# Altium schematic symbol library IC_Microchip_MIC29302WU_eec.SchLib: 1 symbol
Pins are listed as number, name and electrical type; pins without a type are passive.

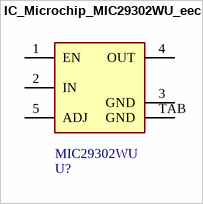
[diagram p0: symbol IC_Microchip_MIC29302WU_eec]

## IC_Microchip_MIC29302WU_eec
designator U?  Part Number: MIC29302WU
IC REG LDO ADJ 3A TO263-5; Manufacturer: Microchip; Voltage: 26V
footprint Microchip_MIC29302WU_0
pins: 1 EN, 2 IN, 3 GND, 4 OUT, 5 ADJ, TAB GND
